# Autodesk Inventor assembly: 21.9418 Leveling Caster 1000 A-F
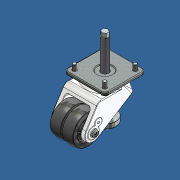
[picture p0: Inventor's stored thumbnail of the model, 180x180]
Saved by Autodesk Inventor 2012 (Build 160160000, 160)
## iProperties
Created: 2015-01
Part Number: 21.9418 Leveling Caster 1000 A-F
Document SubType Name: Assembly
Designer: Admin
Author: Admin
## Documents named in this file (7)
- C:\Andys Backup Data\ANDY'S INVENTOR\INVENTOR LIBRARIES\PARTS LIBRARY\FEET WHEELS FLOOR FASTENING SUPPORTS\21.9418 Leveling Caster 1000 A-F.iam
- C:\Andys Backup Data\ANDY'S INVENTOR\INVENTOR LIBRARIES\PARTS LIBRARY\FEET WHEELS FLOOR FASTENING SUPPORTS\SUBCOMPONENTS\21.9418 Leveling Caster 1000 A-F Leveler.ipt
- C:\Andys Backup Data\ANDY'S INVENTOR\INVENTOR LIBRARIES\PARTS LIBRARY\FEET WHEELS FLOOR FASTENING SUPPORTS\SUBCOMPONENTS\21.9418 Leveling Caster 1000 A-F Fork.ipt
- C:\Andys Backup Data\ANDY'S INVENTOR\INVENTOR LIBRARIES\PARTS LIBRARY\FEET WHEELS FLOOR FASTENING SUPPORTS\SUBCOMPONENTS\21.9418 Leveling Caster 1000 A-F Wheel.ipt
- C:\Andys Backup Data\ANDY'S INVENTOR\INVENTOR LIBRARIES\PARTS LIBRARY\FEET WHEELS FLOOR FASTENING SUPPORTS\SUBCOMPONENTS\21.9418 Leveling Caster 1000 A-F Bearing Ring.ipt
- C:\Andys Backup Data\ANDY'S INVENTOR\INVENTOR LIBRARIES\PARTS LIBRARY\FASTENING ELEMENTS\SCREWS OTHER\HEX BOLT M8X20.ipt
- C:\Andys Backup Data\ANDY'S INVENTOR\INVENTOR LIBRARIES\PARTS LIBRARY\FASTENING ELEMENTS\NUTS\21.1526 M8 HEX NUT.ipt
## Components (13 placed, 6 different names)
1. 21.9418 Leveling Caster 1000 A-F Leveler:1 — Mate:1, Mate:2, Tangent:1, Flush:1, Angle:1, Insert:1, Insert:2, Insert:3, Insert:4
2. 21.9418 Leveling Caster 1000 A-F Fork:1 — Mate:1, Mate:3, Mate:4, Flush:1, Mate:5, Mate:6, Angle:1
3. 21.9418 Leveling Caster 1000 A-F Wheel:1 — Mate:3, Mate:6
4. 21.9418 Leveling Caster 1000 A-F Wheel:2 — Mate:4, Mate:5
5. 21.9418 Leveling Caster 1000 A-F Bearing Ring:1 — Mate:2, Tangent:1
6. HEX BOLT M8X20 DIN 931:1 — Insert:1, Insert:5
7. HEX BOLT M8X20 DIN 931:2 — Insert:2, Insert:8
8. HEX BOLT M8X20 DIN 931:3 — Insert:3, Insert:7
9. HEX BOLT M8X20 DIN 931:4 — Insert:4, Insert:6
10. 21.1526 M8 HEX NUT:1 — Insert:6
11. 21.1526 M8 HEX NUT:2 — Insert:7
12. 21.1526 M8 HEX NUT:3 — Insert:5
13. 21.1526 M8 HEX NUT:4 — Insert:8
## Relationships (17: Insert 8, Mate 6, Tangent 1, Flush 1, Angle 1)
- Mate:1: 21.9418 Leveling Caster 1000 A-F Leveler:1 ↔ 21.9418 Leveling Caster 1000 A-F Fork:1
- Mate:2: 21.9418 Leveling Caster 1000 A-F Leveler:1 ↔ 21.9418 Leveling Caster 1000 A-F Bearing Ring:1
- Mate:3: 21.9418 Leveling Caster 1000 A-F Fork:1 ↔ 21.9418 Leveling Caster 1000 A-F Wheel:1
- Mate:4: 21.9418 Leveling Caster 1000 A-F Fork:1 ↔ 21.9418 Leveling Caster 1000 A-F Wheel:2
- Tangent:1: 21.9418 Leveling Caster 1000 A-F Leveler:1 ↔ 21.9418 Leveling Caster 1000 A-F Bearing Ring:1
- Flush:1: 21.9418 Leveling Caster 1000 A-F Leveler:1 ↔ 21.9418 Leveling Caster 1000 A-F Fork:1
- Mate:5: 21.9418 Leveling Caster 1000 A-F Fork:1 ↔ 21.9418 Leveling Caster 1000 A-F Wheel:2
- Mate:6: 21.9418 Leveling Caster 1000 A-F Fork:1 ↔ 21.9418 Leveling Caster 1000 A-F Wheel:1
- Angle:1: 21.9418 Leveling Caster 1000 A-F Leveler:1 ↔ 21.9418 Leveling Caster 1000 A-F Fork:1
- Insert:1: 21.9418 Leveling Caster 1000 A-F Leveler:1 ↔ HEX BOLT M8X20 DIN 931:1
- Insert:2: 21.9418 Leveling Caster 1000 A-F Leveler:1 ↔ HEX BOLT M8X20 DIN 931:2
- Insert:3: 21.9418 Leveling Caster 1000 A-F Leveler:1 ↔ HEX BOLT M8X20 DIN 931:3
- Insert:4: 21.9418 Leveling Caster 1000 A-F Leveler:1 ↔ HEX BOLT M8X20 DIN 931:4
- Insert:5: HEX BOLT M8X20 DIN 931:1 ↔ 21.1526 M8 HEX NUT:3
- Insert:6: HEX BOLT M8X20 DIN 931:4 ↔ 21.1526 M8 HEX NUT:1
- Insert:7: HEX BOLT M8X20 DIN 931:3 ↔ 21.1526 M8 HEX NUT:2
- Insert:8: HEX BOLT M8X20 DIN 931:2 ↔ 21.1526 M8 HEX NUT:4
